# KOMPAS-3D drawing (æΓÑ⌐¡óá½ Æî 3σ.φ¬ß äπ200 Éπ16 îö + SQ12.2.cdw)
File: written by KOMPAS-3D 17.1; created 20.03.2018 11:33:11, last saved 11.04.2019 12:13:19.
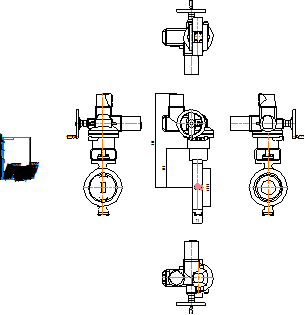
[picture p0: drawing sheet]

Sheet 1: A4, portrait

Title block, sheet 1: name: Стейнвал ТМ 3х.экс / Ду200 Ру16 МФ + SQ12.2; material: Внимание! Данный продукт является объектом авторского права ООО «Торговый Дом АДЛ». / Запрещается изменение, копирование, распространение / (в том числе путем копирования на другие сайты и ресурсы в Интернете) / или любое иное использование информации и объектов без предварительного / согласия правообладателя (ООО «Торговый Дом АДЛ»).; mass: 97,3; sheets: 1; organisation: ООО "Торговый дом АДЛ"; sheet format: A4; stored path: \\adlc.lan\data\АДЛ_ПКД\3D-модели\ADL production\Дисковые поворотные затворы СТЕЙНВАЛ\Трехэксцентриковый\Стейнвал м-ф\С эл.приводом\KOMPAS 2D\Стейнвал ТМ 3х.экс Ду200 Ру16 МФ + SQ12.2.cdw

Views: Вид 1, Проекционный вид 3, Проекционный вид 4, Проекционный вид 5
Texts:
  kka
  adl
Dimensions and other numbers on the sheet: 71; 270; 655; 268; 1:1; 1; 97,3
